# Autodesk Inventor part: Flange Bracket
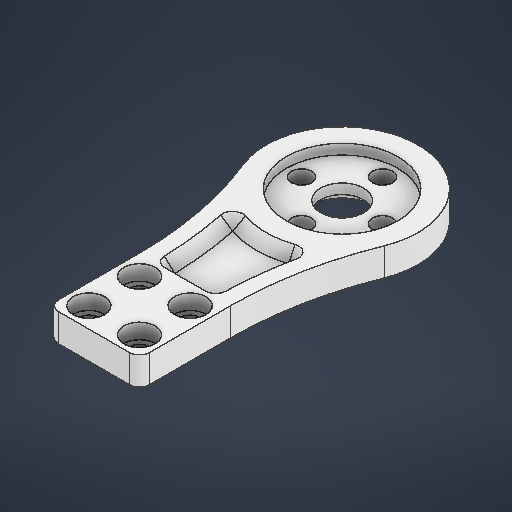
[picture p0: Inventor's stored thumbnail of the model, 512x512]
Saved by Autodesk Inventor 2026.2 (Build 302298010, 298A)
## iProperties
Created: 2026-05
Part Number: Flange Bracket
Material: ABS 플라스틱
Document SubType Name: Modeling
Designer: work
Density: 1.06 g/cm^3
Appearance: 매끄러움 - 흰색
Author: work
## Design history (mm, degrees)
sketch "스케치1"
  geometry: L1 (-5, 5)-(5, 5); L2 (5, 5)-(5, -5); L3 (5, -5)-(-5, -5); L4 (-5, -5)-(-5, 5); L5 (-5, 5)-(5, -5); L6 (5, 5)-(-5, -5); L7 (-9, 9)-(9, 9); L8 (9, 9)-(9, -9); L9 (9, -9)-(-9, -9); L10 (-9, -9)-(-9, 9); L11 (-9, 9)-(9, -9); L12 (9, 9)-(-9, -9); L13 (0, -40)-(8, -40); L14 (0, -40)-(0, 0); L15 (0, -40)-(0, -32); L16 (0, -40)-(-8, -40); L17 (0, -40)-(0, -48); L18 (6, -9)-(6, 9); C1 r 2 at (5, 5); C2 r 2 at (5, -5); C3 r 2 at (-5, -5); C4 r 2 at (-5, 5); C5 r 11 at (0, -40); C6 r 4.25 at (0, -40); C7 r 2 at (8, -40); C8 r 2 at (0, -32); C9 r 2 at (-8, -40); C10 r 2 at (0, -48); A1 r 15 centre (0, -40) between (13.917, -34.403) and (8.485, -27.63); A2 r 68.083 centre (77.083, -9) between (9, -9) and (13.917, -34.403); A3 r 68.083 centre (-77.083, -9) between (-13.917, -34.403) and (-9, -9); A4 r 71.083 centre (77.083, -9) between (6, -9) and (8.485, -27.63); A5 r 71.083 centre (-77.083, -9) between (-8.485, -27.63) and (-6, -9); 3 further points
  constraints: 36 end point, 15 centre point, 10 coincident, 10 point on circle, 5 symmetric about line, 4 midpoint, 4 parallel, 3 horizontal, 3 perpendicular, 3 tangent, 2 point on line, 1 concentric, 1 vertical, 23 other
  dimensions: "d0" = 10 distance of L2.end L3.end; "d1" = 10 distance of L1.end L2.end; "d2" = 4 diameter of C1; "d3" = 4 diameter of C2; "d4" = 4 diameter of C3; "d5" = 4 diameter of C4; "d6" = 18 distance of L8.end L9.end; "d7" = 18 distance of L7.end L8.end; "d8" = 22 diameter of C5; "d9" = 8 distance of L13.start L13.end; "d10" = 8.5 diameter of C6; "d11" = 40 distance of L14.start L14.end; "d12" = 4 diameter of C7; "d15" = 360 deg dimension on L14.start L13.end (derived); "d17" = 30 diameter of A1; "d18" = 3 distance between parallel lines of L8 L18
  node "스케치 - 원형 패턴1" dims "d15" = 360 deg (derived)
extrude "돌출1" new body sketch "스케치1" distance "d19" = 6; taper "d20" = 0 deg
extrude "돌출2" join sketch "스케치1" distance "d21" = 4; taper "d22" = 0 deg
fillet "모깎기1" dims "d23" = 2
chamfer "모따기1" distance "d24" = 2; stored, may be unused: second distance "d25" = 2, angle "d26" = 45 deg
sketch "스케치2"
  geometry: C1 r 2 at (5, 5) reference; C2 r 2 at (5, -5) reference; C3 r 2 at (-5, 5) reference; C4 r 2 at (-5, -5) reference; 5 further points
  constraints: 4 coincident
hole "구멍1" sketch "스케치2" at (5, 5), (5, -5), (-5, 5), (-5, -5) diameter "d27" = 4; stored, may be unused: countersink angle "d31" = 90 deg, drill point angle "d33" = 118 deg; dims "d28" = 6, "d29" = 6.2, "d30" = 3, "d32" = 8
chamfer "모따기2" distance "d34" = 0.5; stored, may be unused: second distance "d35" = 2, angle "d36" = 45 deg
node "솔리드1"
feature "A9D066F2-1C7D-4E18-AEED-F7BC21143FA4" dims "d27" = 4, "d28" = 6, "d29" = 6.2, "d30" = 3, "d31" = 90 deg, "d32" = 8, "d33" = 118 deg
